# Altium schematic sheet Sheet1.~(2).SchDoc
size A4
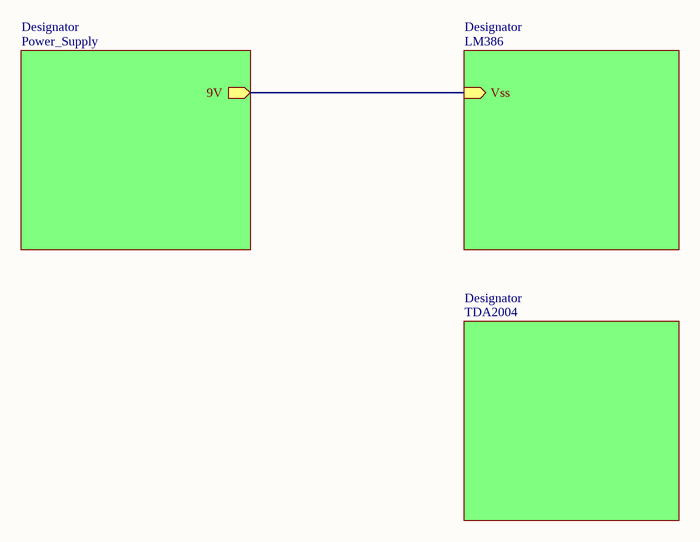
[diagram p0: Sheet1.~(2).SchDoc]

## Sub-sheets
Designator = Power_Supply: 9V (out)
Designator = LM386: Vss (in)
Designator = TDA2004: no entries

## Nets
(unnamed): sheet Designator/9V, sheet Designator/Vss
